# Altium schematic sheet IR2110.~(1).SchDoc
size A4
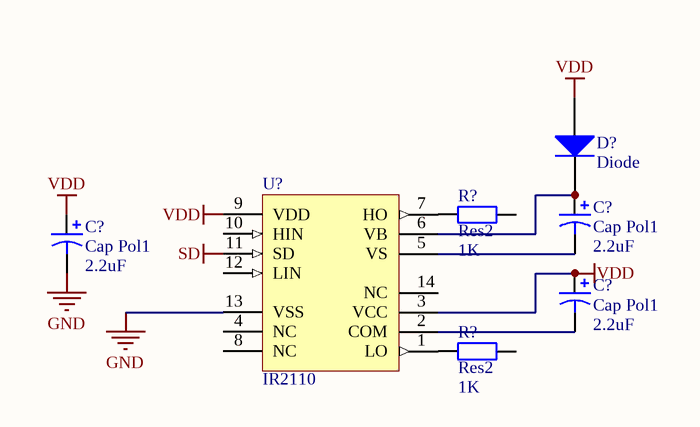
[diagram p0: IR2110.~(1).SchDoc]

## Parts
(Parts that share a designator on the sheet are numbered #1, #2 ... from top to bottom, then left to right.)
C?#1  Cap Pol1  value 2.2uF  [RB7.6-15]
C?#2  Cap Pol1  value 2.2uF  [RB7.6-15]
C?#3  Cap Pol1  value 2.2uF  [RB7.6-15]
D?  Diode  [SMC]
R?#1  Res2  value 1K  [AXIAL-0.4]
R?#2  Res2  value 1K  [AXIAL-0.4]
U?  IR2110  [PDIP14]

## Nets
GND: C?#2.2 U?.13(VSS)
SD: U?.11(SD)
VDD: C?#2.1 C?#3.1 D?.1(A) U?.3(VCC) U?.9(VDD)
NetC?#1_1: C?#1.1 D?.2(K) U?.6(VB)
NetC?#1_2: C?#1.2 U?.5(VS)
NetC?#3_2: C?#3.2 U?.2(COM)
NetR?#1_1: R?#1.1 U?.7(HO)
NetR?#2_1: R?#2.1 U?.1(LO)

Not connected (* = marked no-connect by the designer): R?#1 2; R?#2 2; U? 4(NC) 8(NC) 10(HIN) 12(LIN) 14(NC)

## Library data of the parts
C?#1-C?#3 = Cap Pol1: Polarized Capacitor (Radial)
D? = Diode: Default Diode
R?#1 R?#2 = Res2: Resistor
U? = IR2110: High and Low Side Driver; Note: Pins 4, 8 and 14 are not connected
